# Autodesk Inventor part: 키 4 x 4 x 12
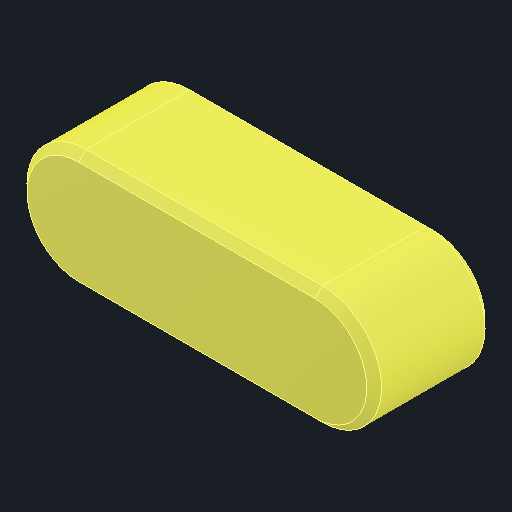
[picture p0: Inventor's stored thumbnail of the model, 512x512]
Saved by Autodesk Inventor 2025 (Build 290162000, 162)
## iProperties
Created: 2025-08
Part Number: 키 4 x 4 x 12
Material: 강철, 연강
Description: 키 및 해당 키홈
Document SubType Name: Modeling
Designer: infra005
Density: 7.85 g/cm^3
Appearance: 기본값
Author: jhkim
Sending System: Autodesk Inventor 2026
Preprocessor: ST-DEVELOPER v20.1
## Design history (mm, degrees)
feature "Solid1"
node "솔리드1"
